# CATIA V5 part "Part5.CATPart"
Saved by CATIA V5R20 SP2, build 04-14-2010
Part number: Part5
Bounding box of the stored display mesh (mm): x -30 to 100, y 87.196 to 529.376, z 98.118 to 279.438
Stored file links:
  E:\Ehsan\Amoozesh\CATIA\CATIA Course\Advanced\Exercises\DMU Kinematic\9\Part5.CATPart
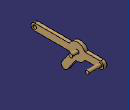
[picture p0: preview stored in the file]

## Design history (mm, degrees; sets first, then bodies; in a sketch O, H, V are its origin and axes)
Body1 (main body)
  Sketch1 on yz-plane, origin (0, 0, 0), H (0, 1, 0), V (0, 0, 1)
    construction line L1 (108.1364, 228.6979) -> (508.4364, 228.6979)
    line L2 (108.1364, 249.6479) -> (321.9233, 249.6479)
    line L3 (508.4364, 207.7479) -> (414.3494, 207.7479)
    arc A1 centre (508.4364, 228.6979) radius 20.95 from (508.4364, 249.6479) to (508.4364, 207.7479) cw
    arc A2 centre (108.1364, 228.6979) radius 20.95 from (108.1364, 207.7479) to (108.1364, 249.6479) cw
    circle A3 centre (508.4364, 228.6979) radius 11.04
    circle A4 centre (108.1364, 228.6979) radius 11.04
    arc A5 centre (368.1364, 228.6979) radius 50.74 from (414.3494, 249.6479) to (321.9233, 249.6479) ccw
    arc A6 centre (368.1364, 228.6979) radius 50.74 from (321.9233, 207.7479) to (324.5046, 202.7978) ccw
    line L4 (414.3494, 249.6479) -> (508.4364, 249.6479)
    line L5 (321.9233, 207.7479) -> (108.1364, 207.7479)
    construction line L6 (368.1364, 228.6979) -> (291.5965, 119.0621)
    line L7 (274.4185, 131.0545) -> (324.5046, 202.7978)
    arc A7 centre (291.5965, 119.0621) radius 20.95 from (308.7745, 107.0696) to (274.4185, 131.0545) cw
    arc A8 centre (368.1364, 228.6979) radius 50.74 from (358.8606, 178.8129) to (414.3494, 207.7479) ccw
    line L8 (358.8606, 178.8129) -> (308.7745, 107.0696)
    circle A9 centre (368.1364, 228.6979) radius 11.04
    circle A10 centre (291.5965, 119.0621) radius 11.04
  MultiPad1: profile Sketch1, domains (length 20; length 20 / length 30; length 60; length 0; length 100)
